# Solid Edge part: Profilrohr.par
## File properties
Username: bmolnar
Dokumentum tartalom típus: 0
Author: bmolnar
Last saved by: bmolnar
Revision: 83
Sűrűség: 0,000 kg/m^3
Pontosság: 0,990
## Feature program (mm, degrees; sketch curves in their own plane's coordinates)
base feature "unnamed BaseFeature 1"
thread "unnamed Thread 1"
thread "Menet_2"  ThreadDepth = 6 mm
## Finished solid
Body 1: solid body, 143 faces, 298 edges, 189 vertices, 3 separate solids.
  Faces by surface: plane 62, cylinder 61, cone 16, torus 4
  Edges by curve: line 156, circle 138, curve on surface 2, spline 2
Bounding box of the edges (mm; curved faces can reach further): 46.000 x 51.000 x 79.500, from (-23, -24, 0) to (23, 27, 79.5).
Cylindrical faces by radius (mm): R0.3 x24, R0.8 x2, R2.5 x2, R2.9 x8, R4.283 x4, R4.35 x2, R4.4 x6, R4.5 x2, R16 x1, R16.85 x2, R17.05 x2, R17.9 x2, R30 x4
Conical faces (half-angle, radius in mm at the cone's reference point): 21 deg R16.325 x2, 30 deg R4.0613 x2, 45 deg R2.75 x4, 45 deg R4.1 x2, 45 deg R4.783 x2, 45 deg R17.1 x2, 45 deg R17.15 x2
Toroidal faces (ring radius, tube radius in mm): R17.7 r0.2 x4
Planar faces by outward normal: +x 6, +y 9, +z 10, -x 6, -y 5, -z 10, oblique 16
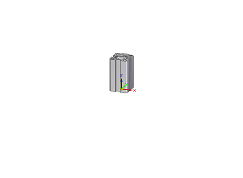
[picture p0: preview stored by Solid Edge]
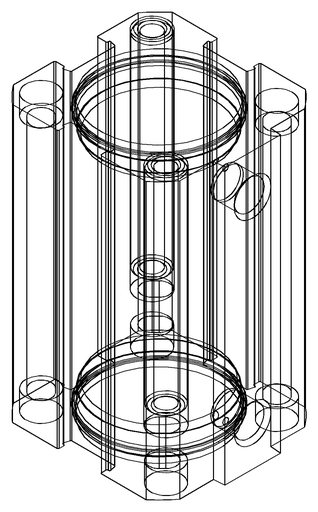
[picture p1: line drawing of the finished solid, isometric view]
